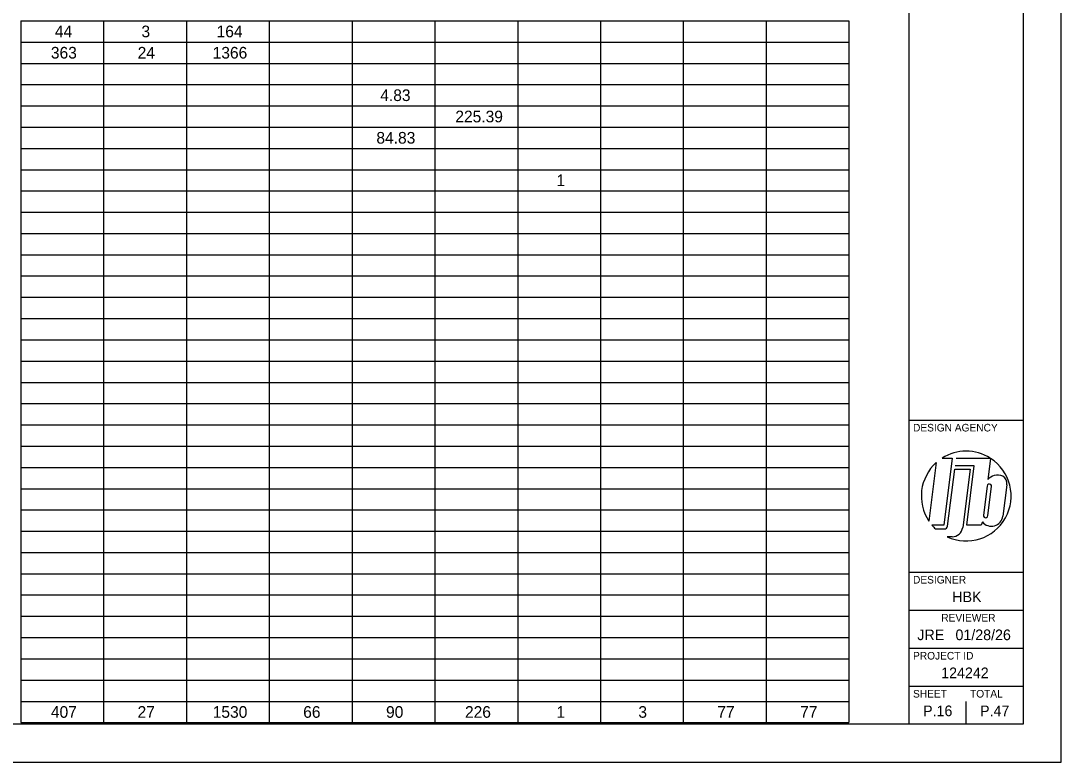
# Model space of a CAD drawing. Extents: x 0 to 34, y 0 to 22.
# Drawn here: x 20.31 to 34, y 0 to 9.75 of the extents above; entities that cross this region are included whole.
import ezdxf

# ---------------------------------------------------------------- set-up
doc = ezdxf.new("R2010")
doc.units = 0
for name, color, linetype in [('Default', 7, 'Continuous'), ('SH_Border', 7, 'Continuous'), ('SH_Cut_Line', 7, 'Continuous'), ('SH_Data', 7, 'Continuous')]:
    doc.layers.add(name, color=color, linetype=linetype)

msp = doc.modelspace()

# ---------------------------------------------------------------- linework, layer by layer
at = {"layer": 'Default'}
for p, q in [((20.307, 9.751), (21.397, 9.751)), ((20.307, 9.751), (20.307, 9.192)), ((21.397, 9.751), (22.487, 9.751)), ((21.397, 9.751), (21.397, 9.192)), ((22.487, 9.751), (23.577, 9.751)), ((22.487, 9.751), (22.487, 9.192)), ((23.577, 9.751), (25.757, 9.751)), ((23.577, 9.751), (23.577, 9.192)), ((24.667, 9.751), (24.667, 9.192)), ((25.757, 9.751), (26.847, 9.751)), ((25.757, 9.751), (25.757, 9.192)), ((26.847, 9.751), (27.937, 9.751)), ((26.847, 9.751), (26.847, 9.192)), ((27.937, 9.751), (29.026, 9.751)), ((27.937, 9.751), (27.937, 9.192)), ((29.026, 9.751), (31.206, 9.751)), ((29.026, 9.751), (29.026, 9.192)), ((30.116, 9.751), (30.116, 9.192)), ((31.206, 9.751), (31.206, 9.192)), ((20.307, 9.472), (21.397, 9.472)), ((21.397, 9.472), (22.487, 9.472)), ((22.487, 9.472), (23.577, 9.472)), ((23.577, 9.472), (25.757, 9.472)), ((25.757, 9.472), (26.847, 9.472)), ((26.847, 9.472), (27.937, 9.472)), ((27.937, 9.472), (29.026, 9.472)), ((29.026, 9.472), (31.206, 9.472)), ((20.307, 9.192), (21.397, 9.192)), ((20.307, 9.192), (20.307, 8.353)), ((21.397, 9.192), (22.487, 9.192)), ((21.397, 9.192), (21.397, 8.353)), ((22.487, 9.192), (23.577, 9.192)), ((22.487, 9.192), (22.487, 8.353)), ((23.577, 9.192), (25.757, 9.192)), ((23.577, 9.192), (23.577, 8.353)), ((24.667, 9.192), (24.667, 8.353)), ((25.757, 9.192), (26.847, 9.192)), ((25.757, 9.192), (25.757, 8.353)), ((26.847, 9.192), (27.937, 9.192)), ((26.847, 9.192), (26.847, 8.353)), ((27.937, 9.192), (29.026, 9.192)), ((27.937, 9.192), (27.937, 8.353)), ((29.026, 9.192), (31.206, 9.192)), ((29.026, 9.192), (29.026, 8.353)), ((30.116, 9.192), (30.116, 8.353)), ((31.206, 9.192), (31.206, 8.353)), ((20.307, 8.912), (21.397, 8.912)), ((21.397, 8.912), (22.487, 8.912)), ((22.487, 8.912), (23.577, 8.912)), ((23.577, 8.912), (25.757, 8.912)), ((25.757, 8.912), (26.847, 8.912)), ((26.847, 8.912), (27.937, 8.912)), ((27.937, 8.912), (29.026, 8.912)), ((29.026, 8.912), (31.206, 8.912)), ((20.307, 8.632), (21.397, 8.632)), ((21.397, 8.632), (22.487, 8.632)), ((22.487, 8.632), (23.577, 8.632)), ((23.577, 8.632), (25.757, 8.632)), ((25.757, 8.632), (26.847, 8.632)), ((26.847, 8.632), (27.937, 8.632)), ((27.937, 8.632), (29.026, 8.632)), ((29.026, 8.632), (31.206, 8.632)), ((20.307, 8.353), (21.397, 8.353)), ((20.307, 8.353), (20.307, 7.793)), ((21.397, 8.353), (22.487, 8.353)), ((21.397, 8.353), (21.397, 7.793)), ((22.487, 8.353), (23.577, 8.353)), ((22.487, 8.353), (22.487, 7.793)), ((23.577, 8.353), (25.757, 8.353)), ((23.577, 8.353), (23.577, 7.793)), ((24.667, 8.353), (24.667, 7.793)), ((25.757, 8.353), (26.847, 8.353)), ((25.757, 8.353), (25.757, 7.793)), ((26.847, 8.353), (27.937, 8.353)), ((26.847, 8.353), (26.847, 7.793)), ((27.937, 8.353), (29.026, 8.353)), ((27.937, 8.353), (27.937, 7.793)), ((29.026, 8.353), (31.206, 8.353)), ((29.026, 8.353), (29.026, 7.793)), ((30.116, 8.353), (30.116, 7.793)), ((31.206, 8.353), (31.206, 7.793)), ((20.307, 8.073), (21.397, 8.073)), ((21.397, 8.073), (22.487, 8.073)), ((22.487, 8.073), (23.577, 8.073)), ((23.577, 8.073), (25.757, 8.073)), ((25.757, 8.073), (26.847, 8.073)), ((26.847, 8.073), (27.937, 8.073)), ((27.937, 8.073), (29.026, 8.073)), ((29.026, 8.073), (31.206, 8.073)), ((20.307, 7.793), (21.397, 7.793)), ((20.307, 7.793), (20.307, 6.954)), ((21.397, 7.793), (22.487, 7.793)), ((21.397, 7.793), (21.397, 6.954)), ((22.487, 7.793), (23.577, 7.793)), ((22.487, 7.793), (22.487, 6.954)), ((23.577, 7.793), (25.757, 7.793)), ((23.577, 7.793), (23.577, 6.954)), ((24.667, 7.793), (24.667, 6.954)), ((25.757, 7.793), (26.847, 7.793)), ((25.757, 7.793), (25.757, 6.954)), ((26.847, 7.793), (27.937, 7.793)), ((26.847, 7.793), (26.847, 6.954)), ((27.937, 7.793), (29.026, 7.793)), ((27.937, 7.793), (27.937, 6.954)), ((29.026, 7.793), (31.206, 7.793)), ((29.026, 7.793), (29.026, 6.954)), ((30.116, 7.793), (30.116, 6.954)), ((31.206, 7.793), (31.206, 6.954)), ((20.307, 7.513), (21.397, 7.513)), ((21.397, 7.513), (22.487, 7.513)), ((22.487, 7.513), (23.577, 7.513)), ((23.577, 7.513), (25.757, 7.513)), ((25.757, 7.513), (26.847, 7.513)), ((26.847, 7.513), (27.937, 7.513)), ((27.937, 7.513), (29.026, 7.513)), ((29.026, 7.513), (31.206, 7.513)), ((20.307, 7.234), (21.397, 7.234)), ((21.397, 7.234), (22.487, 7.234)), ((22.487, 7.234), (23.577, 7.234)), ((23.577, 7.234), (25.757, 7.234)), ((25.757, 7.234), (26.847, 7.234)), ((26.847, 7.234), (27.937, 7.234)), ((27.937, 7.234), (29.026, 7.234)), ((29.026, 7.234), (31.206, 7.234)), ((20.307, 6.954), (21.397, 6.954)), ((20.307, 6.954), (20.307, 6.395)), ((21.397, 6.954), (22.487, 6.954)), ((21.397, 6.954), (21.397, 6.395)), ((22.487, 6.954), (23.577, 6.954)), ((22.487, 6.954), (22.487, 6.395)), ((23.577, 6.954), (25.757, 6.954)), ((23.577, 6.954), (23.577, 6.395)), ((24.667, 6.954), (24.667, 6.395)), ((25.757, 6.954), (26.847, 6.954)), ((25.757, 6.954), (25.757, 6.395)), ((26.847, 6.954), (27.937, 6.954)), ((26.847, 6.954), (26.847, 6.395)), ((27.937, 6.954), (29.026, 6.954)), ((27.937, 6.954), (27.937, 6.395)), ((29.026, 6.954), (31.206, 6.954)), ((29.026, 6.954), (29.026, 6.395)), ((30.116, 6.954), (30.116, 6.395)), ((31.206, 6.954), (31.206, 6.395)), ((20.307, 6.674), (21.397, 6.674)), ((21.397, 6.674), (22.487, 6.674)), ((22.487, 6.674), (23.577, 6.674)), ((23.577, 6.674), (25.757, 6.674)), ((25.757, 6.674), (26.847, 6.674)), ((26.847, 6.674), (27.937, 6.674)), ((27.937, 6.674), (29.026, 6.674)), ((29.026, 6.674), (31.206, 6.674)), ((20.307, 6.395), (21.397, 6.395)), ((20.307, 6.395), (20.307, 0.52)), ((21.397, 6.395), (22.487, 6.395)), ((21.397, 6.395), (21.397, 0.52)), ((22.487, 6.395), (23.577, 6.395)), ((22.487, 6.395), (22.487, 0.52)), ((23.577, 6.395), (25.757, 6.395)), ((23.577, 6.395), (23.577, 0.52)), ((24.667, 6.395), (24.667, 0.52)), ((25.757, 6.395), (26.847, 6.395)), ((25.757, 6.395), (25.757, 0.52)), ((26.847, 6.395), (27.937, 6.395)), ((26.847, 6.395), (26.847, 0.52)), ((27.937, 6.395), (29.026, 6.395)), ((27.937, 6.395), (27.937, 0.52)), ((29.026, 6.395), (31.206, 6.395)), ((29.026, 6.395), (29.026, 0.52)), ((30.116, 6.395), (30.116, 0.52)), ((31.206, 6.395), (31.206, 0.52)), ((20.307, 6.115), (21.397, 6.115)), ((21.397, 6.115), (22.487, 6.115)), ((22.487, 6.115), (23.577, 6.115)), ((23.577, 6.115), (25.757, 6.115)), ((25.757, 6.115), (26.847, 6.115)), ((26.847, 6.115), (27.937, 6.115)), ((27.937, 6.115), (29.026, 6.115)), ((29.026, 6.115), (31.206, 6.115)), ((20.307, 5.835), (21.397, 5.835)), ((21.397, 5.835), (22.487, 5.835)), ((22.487, 5.835), (23.577, 5.835)), ((23.577, 5.835), (25.757, 5.835)), ((25.757, 5.835), (26.847, 5.835)), ((26.847, 5.835), (27.937, 5.835)), ((27.937, 5.835), (29.026, 5.835)), ((29.026, 5.835), (31.206, 5.835)), ((20.307, 5.555), (21.397, 5.555)), ((21.397, 5.555), (22.487, 5.555)), ((22.487, 5.555), (23.577, 5.555)), ((23.577, 5.555), (25.757, 5.555)), ((25.757, 5.555), (26.847, 5.555)), ((26.847, 5.555), (27.937, 5.555)), ((27.937, 5.555), (29.026, 5.555)), ((29.026, 5.555), (31.206, 5.555)), ((20.307, 5.276), (21.397, 5.276)), ((21.397, 5.276), (22.487, 5.276)), ((22.487, 5.276), (23.577, 5.276)), ((23.577, 5.276), (25.757, 5.276)), ((25.757, 5.276), (26.847, 5.276)), ((26.847, 5.276), (27.937, 5.276)), ((27.937, 5.276), (29.026, 5.276)), ((29.026, 5.276), (31.206, 5.276)), ((20.307, 4.996), (21.397, 4.996)), ((21.397, 4.996), (22.487, 4.996)), ((22.487, 4.996), (23.577, 4.996)), ((23.577, 4.996), (25.757, 4.996)), ((25.757, 4.996), (26.847, 4.996)), ((26.847, 4.996), (27.937, 4.996)), ((27.937, 4.996), (29.026, 4.996)), ((29.026, 4.996), (31.206, 4.996)), ((20.307, 4.716), (21.397, 4.716)), ((21.397, 4.716), (22.487, 4.716)), ((22.487, 4.716), (23.577, 4.716)), ((23.577, 4.716), (25.757, 4.716)), ((25.757, 4.716), (26.847, 4.716)), ((26.847, 4.716), (27.937, 4.716)), ((27.937, 4.716), (29.026, 4.716)), ((29.026, 4.716), (31.206, 4.716)), ((20.307, 4.436), (21.397, 4.436)), ((21.397, 4.436), (22.487, 4.436)), ((22.487, 4.436), (23.577, 4.436)), ((23.577, 4.436), (25.757, 4.436)), ((25.757, 4.436), (26.847, 4.436)), ((26.847, 4.436), (27.937, 4.436)), ((27.937, 4.436), (29.026, 4.436)), ((29.026, 4.436), (31.206, 4.436)), ((20.307, 4.157), (21.397, 4.157)), ((21.397, 4.157), (22.487, 4.157)), ((22.487, 4.157), (23.577, 4.157)), ((23.577, 4.157), (25.757, 4.157)), ((25.757, 4.157), (26.847, 4.157)), ((26.847, 4.157), (27.937, 4.157)), ((27.937, 4.157), (29.026, 4.157)), ((29.026, 4.157), (31.206, 4.157)), ((20.307, 3.877), (21.397, 3.877)), ((21.397, 3.877), (22.487, 3.877)), ((22.487, 3.877), (23.577, 3.877)), ((23.577, 3.877), (25.757, 3.877)), ((25.757, 3.877), (26.847, 3.877)), ((26.847, 3.877), (27.937, 3.877)), ((27.937, 3.877), (29.026, 3.877)), ((29.026, 3.877), (31.206, 3.877)), ((20.307, 3.597), (21.397, 3.597)), ((21.397, 3.597), (22.487, 3.597)), ((22.487, 3.597), (23.577, 3.597)), ((23.577, 3.597), (25.757, 3.597)), ((25.757, 3.597), (26.847, 3.597)), ((26.847, 3.597), (27.937, 3.597)), ((27.937, 3.597), (29.026, 3.597)), ((29.026, 3.597), (31.206, 3.597)), ((20.307, 3.318), (21.397, 3.318)), ((21.397, 3.318), (22.487, 3.318)), ((22.487, 3.318), (23.577, 3.318)), ((23.577, 3.318), (25.757, 3.318)), ((25.757, 3.318), (26.847, 3.318)), ((26.847, 3.318), (27.937, 3.318)), ((27.937, 3.318), (29.026, 3.318)), ((29.026, 3.318), (31.206, 3.318)), ((20.307, 3.038), (21.397, 3.038)), ((21.397, 3.038), (22.487, 3.038)), ((22.487, 3.038), (23.577, 3.038)), ((23.577, 3.038), (25.757, 3.038)), ((25.757, 3.038), (26.847, 3.038)), ((26.847, 3.038), (27.937, 3.038)), ((27.937, 3.038), (29.026, 3.038)), ((29.026, 3.038), (31.206, 3.038)), ((20.307, 2.758), (21.397, 2.758)), ((21.397, 2.758), (22.487, 2.758)), ((22.487, 2.758), (23.577, 2.758)), ((23.577, 2.758), (25.757, 2.758)), ((25.757, 2.758), (26.847, 2.758)), ((26.847, 2.758), (27.937, 2.758)), ((27.937, 2.758), (29.026, 2.758)), ((29.026, 2.758), (31.206, 2.758)), ((20.307, 2.478), (21.397, 2.478)), ((21.397, 2.478), (22.487, 2.478)), ((22.487, 2.478), (23.577, 2.478)), ((23.577, 2.478), (25.757, 2.478)), ((25.757, 2.478), (26.847, 2.478)), ((26.847, 2.478), (27.937, 2.478)), ((27.937, 2.478), (29.026, 2.478)), ((29.026, 2.478), (31.206, 2.478)), ((20.307, 2.199), (21.397, 2.199)), ((21.397, 2.199), (22.487, 2.199)), ((22.487, 2.199), (23.577, 2.199)), ((23.577, 2.199), (25.757, 2.199)), ((25.757, 2.199), (26.847, 2.199)), ((26.847, 2.199), (27.937, 2.199)), ((27.937, 2.199), (29.026, 2.199)), ((29.026, 2.199), (31.206, 2.199)), ((20.307, 1.919), (21.397, 1.919)), ((21.397, 1.919), (22.487, 1.919)), ((22.487, 1.919), (23.577, 1.919)), ((23.577, 1.919), (25.757, 1.919)), ((25.757, 1.919), (26.847, 1.919)), ((26.847, 1.919), (27.937, 1.919)), ((27.937, 1.919), (29.026, 1.919)), ((29.026, 1.919), (31.206, 1.919)), ((20.307, 1.639), (21.397, 1.639)), ((21.397, 1.639), (22.487, 1.639)), ((22.487, 1.639), (23.577, 1.639)), ((23.577, 1.639), (25.757, 1.639)), ((25.757, 1.639), (26.847, 1.639)), ((26.847, 1.639), (27.937, 1.639)), ((27.937, 1.639), (29.026, 1.639)), ((29.026, 1.639), (31.206, 1.639)), ((20.307, 1.359), (21.397, 1.359)), ((21.397, 1.359), (22.487, 1.359)), ((22.487, 1.359), (23.577, 1.359)), ((23.577, 1.359), (25.757, 1.359)), ((25.757, 1.359), (26.847, 1.359)), ((26.847, 1.359), (27.937, 1.359)), ((27.937, 1.359), (29.026, 1.359)), ((29.026, 1.359), (31.206, 1.359)), ((20.307, 1.08), (21.397, 1.08)), ((21.397, 1.08), (22.487, 1.08)), ((22.487, 1.08), (23.577, 1.08)), ((23.577, 1.08), (25.757, 1.08)), ((25.757, 1.08), (26.847, 1.08)), ((26.847, 1.08), (27.937, 1.08)), ((27.937, 1.08), (29.026, 1.08)), ((29.026, 1.08), (31.206, 1.08)), ((20.307, 0.8), (21.397, 0.8)), ((21.397, 0.8), (22.487, 0.8)), ((22.487, 0.8), (23.577, 0.8)), ((23.577, 0.8), (25.757, 0.8)), ((25.757, 0.8), (26.847, 0.8)), ((26.847, 0.8), (27.937, 0.8)), ((27.937, 0.8), (29.026, 0.8)), ((29.026, 0.8), (31.206, 0.8)), ((20.307, 0.52), (21.397, 0.52)), ((21.397, 0.52), (22.487, 0.52)), ((22.487, 0.52), (23.577, 0.52)), ((23.577, 0.52), (25.757, 0.52)), ((25.757, 0.52), (26.847, 0.52)), ((26.847, 0.52), (27.937, 0.52)), ((27.937, 0.52), (29.026, 0.52)), ((29.026, 0.52), (31.206, 0.52))]:
    msp.add_line(p, q, dxfattribs=at)
at = {"layer": 'SH_Border'}
for p, q in [((32, 0.5), (32, 21.5)), ((32, 4.5), (33.5, 4.5)), ((32, 2.5), (33.5, 2.5)), ((32, 2), (33.5, 2)), ((32, 1.5), (33.5, 1.5)), ((32, 1), (33.5, 1))]:
    msp.add_line(p, q, dxfattribs=at)
msp.add_lwpolyline([(1.5, 21.5), (33.5, 21.5), (33.5, 0.5), (1.5, 0.5)], close=True, dxfattribs=at)
at = {"layer": 'SH_Cut_Line'}
msp.add_lwpolyline([(0, 0), (34, 0), (34, 22), (0, 22)], close=True, dxfattribs=at)
at = {"layer": 'SH_Data'}
for p, q in [((32.432, 3.998), (32.567, 3.998)), ((32.567, 3.998), (32.456, 3.118)), ((32.617, 4), (33.065, 4)), ((33.07, 3.996), (33.035, 3.72)), ((32.356, 3.94), (32.259, 3.171)), ((32.504, 3.104), (32.599, 3.855)), ((32.599, 3.855), (32.801, 3.855)), ((32.856, 3.896), (32.604, 3.896)), ((32.801, 3.855), (32.704, 3.089)), ((32.758, 3.118), (32.856, 3.896)), ((33.024, 3.631), (32.976, 3.25)), ((33.036, 3.243), (33.084, 3.624)), ((33.283, 3.648), (33.231, 3.237)), ((32.75, 3.5), (32.75, 3.5)), ((32.964, 3.161), (32.947, 3.118)), ((32.456, 3.118), (32.299, 3.118)), ((32.347, 3.068), (32.462, 3.068)), ((32.947, 3.118), (32.758, 3.118)), ((32.564, 2.966), (32.498, 2.966)), ((32.75, 0.5), (32.75, 0.8)), ((32.375, 0.675), (32.375, 0.675))]:
    msp.add_line(p, q, dxfattribs=at)
for centre, radius, start, end in [((32.75, 3.5), 0.591, 57.726, 122.5688), ((32.75, 3.5), 0.591, 244.7646, 57.1575), ((32.75, 3.5), 0.591, 131.8253, 213.7822), ((33.17, 3.586), 0.19, 105.9444, 135.0487), ((33.164, 3.6), 0.175, 66.6782, 105.4185), ((33.177, 3.669), 0.108, 349.2072, 58.7163), ((33.054, 3.628), 0.0301, 352.3298, 173.2777), ((33.081, 3.255), 0.151, 218.6264, 353.0883), ((33.006, 3.246), 0.0301, 172.3335, 353.274), ((32.75, 3.5), 0.591, 220.2786, 227.0158), ((32.462, 3.109), 0.0417, 270, 352.8038), ((32.564, 3.106), 0.141, 270, 352.8038)]:
    msp.add_arc(centre, radius, start, end, dxfattribs=at)

# ---------------------------------------------------------------- texts
at = {"layer": 'Default'}
for s, height, p in [('44', 0.1532, (20.755, 9.535)), ('3', 0.153, (21.895, 9.535)), ('164', 0.1532, (22.884, 9.535)), ('363', 0.1532, (20.703, 9.255)), ('24', 0.1532, (21.845, 9.255)), ('1366', 0.1532, (22.832, 9.255)), ('4.83', 0.1532, (25.038, 8.696)), ('225.39', 0.1532, (26.026, 8.416)), ('84.83', 0.1532, (24.987, 8.136)), ('1', 0.153, (27.357, 7.577)), ('407', 0.1532, (20.703, 0.584)), ('27', 0.1532, (21.844, 0.584)), ('1530', 0.1532, (22.833, 0.584)), ('66', 0.1532, (24.024, 0.584)), ('90', 0.1532, (25.114, 0.584)), ('226', 0.1532, (26.153, 0.584)), ('1', 0.153, (27.357, 0.584)), ('3', 0.153, (28.435, 0.584)), ('77', 0.1532, (29.474, 0.584)), ('77', 0.1532, (30.564, 0.584))]:
    msp.add_text(s, height=height, dxfattribs=at).set_placement(p)
at = {"layer": 'SH_Data'}
for s, height, p in [('DESIGN AGENCY', 0.1, (32.05, 4.35)), ('DESIGNER', 0.1, (32.05, 2.35)), ('HBK', 0.14, (32.567, 2.105)), ('REVIEWER', 0.1, (32.422, 1.85)), ('JRE', 0.14, (32.107, 1.605)), ('01/28/26', 0.14, (32.609, 1.605)), ('PROJECT ID', 0.1, (32.05, 1.35)), ('124242', 0.14, (32.421, 1.105)), ('SHEET', 0.1, (32.05, 0.85)), ('TOTAL', 0.1, (32.8, 0.85)), ('P.16', 0.14, (32.183, 0.605)), ('P.47', 0.14, (32.933, 0.605))]:
    msp.add_text(s, height=height, dxfattribs=at).set_placement(p)

doc.saveas('drawing.dxf')
